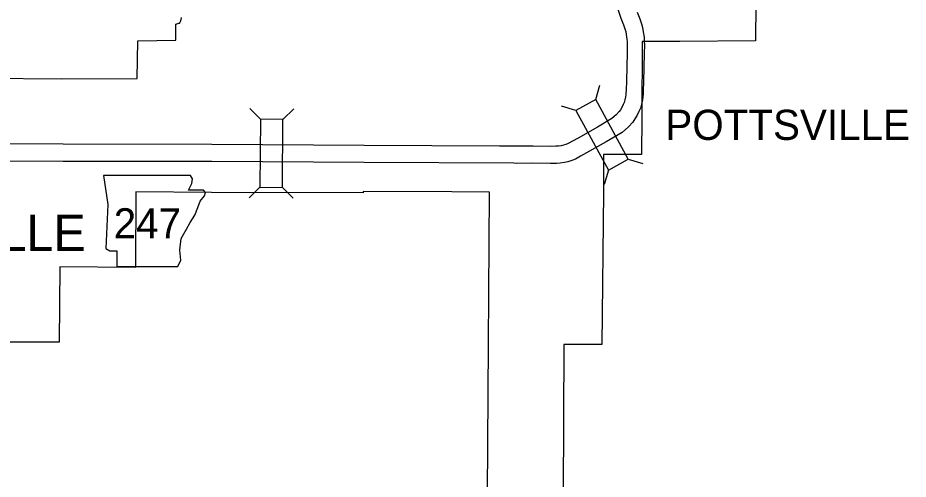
# Model space of a CAD drawing. Extents: x 1374139 to 1377472, y 1168351 to 1170484.
# Drawn here: x 1374573.9 to 1374729.7, y 1169894.4 to 1169975.1 of the extents above; entities that cross this region are included whole.
import ezdxf

# ---------------------------------------------------------------- set-up
doc = ezdxf.new("R2010")
doc.units = 0
doc.layers.add('Default', color=7, linetype='Continuous')

msp = doc.modelspace()

# ---------------------------------------------------------------- linework, layer by layer
at = {"layer": 'Default'}
for p, q in [((1374675.03, 1169960.8), (1374675.78, 1169963.33)), ((1374616.37, 1169957.36), (1374614.51, 1169959.24)), ((1374620.33, 1169957.33), (1374622.21, 1169959.19)), ((1374671.56, 1169958.9), (1374669.02, 1169959.65)), ((1374680.72, 1169950.37), (1374683.26, 1169949.63)), ((1374677.25, 1169948.47), (1374676.5, 1169945.94)), ((1374616.29, 1169945.48), (1374614.41, 1169943.62)), ((1374620.25, 1169945.45), (1374622.11, 1169943.57))]:
    msp.add_line(p, q, dxfattribs=at)
for points in [[(1374657.04, 1170017.47), (1374663.55, 1170017.44), (1374663.54, 1170010.76), (1374676.85, 1170010.66), (1374689.94, 1170010.57), (1374703.21, 1170010.61), (1374703.24, 1169997.37), (1374703.01, 1169971.08), (1374689.77, 1169970.99), (1374683.16, 1169970.99), (1374683.1, 1169957.78), (1374683.06, 1169951.17), (1374676.42, 1169951.17), (1374676.38, 1169944.56), (1374676.11, 1169917.93), (1374669.48, 1169917.94)], [(1374678.9, 1169976.65), (1374679.45, 1169975.03), (1374679.92, 1169973.89), (1374680.15, 1169973.21), (1374680.28, 1169972.73), (1374680.38, 1169972.18), (1374680.49, 1169971.4), (1374680.53, 1169970.93), (1374680.56, 1169970.23), (1374680.53, 1169969.15), (1374680.45, 1169966.4), (1374680.4, 1169964.12), (1374680.35, 1169962.4), (1374680.33, 1169961.99), (1374680.3, 1169961.61), (1374680.26, 1169961.29), (1374680.14, 1169960.77), (1374680, 1169960.32), (1374679.86, 1169959.96), (1374679.64, 1169959.53), (1374679.34, 1169959.03), (1374679.12, 1169958.7), (1374678.63, 1169958.15), (1374677.88, 1169957.5), (1374675.37, 1169955.98), (1374671.99, 1169954.08), (1374670.98, 1169953.52), (1374670.2, 1169953.11), (1374669.8, 1169952.95), (1374669.38, 1169952.81), (1374669.01, 1169952.73), (1374668.52, 1169952.65), (1374668.07, 1169952.63), (1374667.11, 1169952.62), (1374664.07, 1169952.66), (1374661.09, 1169952.65), (1374658.21, 1169952.68)], [(1374682.26, 1169976.08), (1374682.73, 1169974.94), (1374683.02, 1169974.09), (1374683.21, 1169973.4), (1374683.35, 1169972.67), (1374683.48, 1169971.74), (1374683.53, 1169971.1), (1374683.56, 1169970.24), (1374683.53, 1169969.07), (1374683.45, 1169966.32), (1374683.4, 1169964.04), (1374683.35, 1169962.3), (1374683.33, 1169961.8), (1374683.28, 1169961.29), (1374683.21, 1169960.75), (1374683.04, 1169960.01), (1374682.84, 1169959.33), (1374682.59, 1169958.72), (1374682.27, 1169958.08), (1374681.87, 1169957.41), (1374681.5, 1169956.86), (1374680.75, 1169956.02), (1374679.65, 1169955.06), (1374676.88, 1169953.39), (1374673.45, 1169951.46), (1374672.4, 1169950.88), (1374671.47, 1169950.4), (1374670.85, 1169950.13), (1374670.17, 1169949.92), (1374669.56, 1169949.78), (1374668.82, 1169949.67), (1374668.16, 1169949.63), (1374667.11, 1169949.62), (1374664.06, 1169949.66), (1374661.09, 1169949.65), (1374660.71, 1169949.67)], [(1374601.58, 1169971.18), (1374601.6, 1169974.03), (1374601.79, 1169974.08), (1374601.96, 1169974.12), (1374602.1, 1169974.16), (1374602.2, 1169974.2), (1374602.26, 1169974.24), (1374602.31, 1169974.29), (1374602.37, 1169974.37), (1374602.41, 1169974.47), (1374602.46, 1169974.61), (1374602.48, 1169974.71), (1374602.52, 1169974.82), (1374602.54, 1169974.94), (1374602.56, 1169975.07), (1374602.57, 1169975.19)], [(1374634.37, 1169944.5), (1374607.84, 1169944.54), (1374594.6, 1169944.68), (1374594.56, 1169931.44), (1374581.27, 1169931.53), (1374581.19, 1169918.33), (1374567.99, 1169918.38), (1374568.09, 1169944.84), (1374568.2, 1169957.99), (1374568.25, 1169964.56), (1374581.54, 1169964.41), (1374594.84, 1169964.49), (1374594.92, 1169971.11), (1374601.58, 1169971.18)], [(1374658.21, 1169952.68), (1374634.52, 1169952.8), (1374607.87, 1169952.97), (1374581.89, 1169952.99), (1374560.25, 1169953.09), (1374550.33, 1169953.33)], [(1374660.71, 1169949.67), (1374634.51, 1169949.8), (1374607.86, 1169949.97), (1374581.88, 1169949.99), (1374560.21, 1169950.09), (1374550.25, 1169950.34)], [(1374656.26, 1169918), (1374656.46, 1169944.6), (1374649.86, 1169944.64), (1374634.37, 1169944.75), (1374634.37, 1169944.5)], [(1374656.1, 1169891.8), (1374656.26, 1169918)], [(1374669.48, 1169917.94), (1374669.34, 1169891.71), (1374669.33, 1169887.7)]]:
    msp.add_lwpolyline(points, dxfattribs=at)
for points in [[(1374671.56, 1169958.9), (1374677.25, 1169948.47), (1374680.72, 1169950.37), (1374675.03, 1169960.8)], [(1374616.37, 1169957.36), (1374616.29, 1169945.48), (1374620.25, 1169945.45), (1374620.33, 1169957.33)], [(1374588.93, 1169947.5), (1374589.69, 1169942.43), (1374589.35, 1169934.73), (1374590.03, 1169934.31), (1374591.29, 1169934.31), (1374591.29, 1169931.6), (1374601.95, 1169931.6), (1374602.46, 1169932.7), (1374602.29, 1169934.48), (1374602.54, 1169936.51), (1374603.48, 1169938.11), (1374604.07, 1169939.3), (1374604.91, 1169940.57), (1374605.42, 1169941.92), (1374605.84, 1169943.02), (1374606.61, 1169943.95), (1374606.77, 1169944.54), (1374606.44, 1169944.97), (1374603.81, 1169944.97), (1374604.41, 1169946.15), (1374604.49, 1169946.91), (1374604.14, 1169947.5)]]:
    msp.add_lwpolyline(points, close=True, dxfattribs=at)

# ---------------------------------------------------------------- texts
for s, height, p in [('POTTSVILLE', 5.28, (1374687.22, 1169953.75)), ('247', 5.28, (1374590.72, 1169936.51)), ('DARDANELLE', 6.336, (1374529.32, 1169934.33))]:
    msp.add_text(s, height=height, dxfattribs=at).set_placement(p)

doc.saveas('drawing.dxf')
